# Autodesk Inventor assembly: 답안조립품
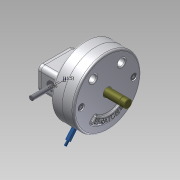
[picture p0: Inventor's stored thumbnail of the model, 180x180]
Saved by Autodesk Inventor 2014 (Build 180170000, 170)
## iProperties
Created: 2015-04
Part Number: 답안조립품
Document SubType Name: Assembly
Designer: Administrator
Mass: 3964.99 g
Surface Area: 3333.71 cm^2
Volume: 1140.85 cm^3
Density: 3.47547 g/cm^3
Author: Administrator
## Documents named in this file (15)
- C:\Documents and Settings\Administrator\바탕 화면\350406V1044\답안조립품.iam
- C:\Documents and Settings\Administrator\바탕 화면\350406V1044\본체.ipt
- C:\Documents and Settings\Administrator\바탕 화면\350406V1044\가변스프링.ipt
- C:\Documents and Settings\Administrator\바탕 화면\350406V1044\부시.ipt
- C:\Documents and Settings\Administrator\바탕 화면\350406V1044\슬라이더3.ipt
- C:\Documents and Settings\Administrator\바탕 화면\350406V1044\축.ipt
- C:\Documents and Settings\Administrator\바탕 화면\350406V1044\멈춤링.ipt
- C:\Documents and Settings\Administrator\바탕 화면\350406V1044\커버2.ipt
- C:\Documents and Settings\Administrator\바탕 화면\350406V1044\M 5 x 12.ipt
- C:\Documents and Settings\Administrator\바탕 화면\350406V1044\베어링62_22.ipt
- C:\Documents and Settings\Administrator\바탕 화면\350406V1044\커버.ipt
- C:\Documents and Settings\Administrator\바탕 화면\350406V1044\M 10 x 35.ipt
- C:\Documents and Settings\Administrator\바탕 화면\350406V1044\슬라이더2.ipt
- C:\Documents and Settings\Administrator\바탕 화면\350406V1044\슬라이더.ipt
- C:\Documents and Settings\Administrator\바탕 화면\350406V1044\평행핀.ipt
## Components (6 placed, 4 different names)
1. 가변스프링:1
2. M 5 x 12:1
3. M 5 x 12:2
4. M 10 x 35:1
5. M 10 x 35:2
6. KS B 1320 B B 5 x  20:1
